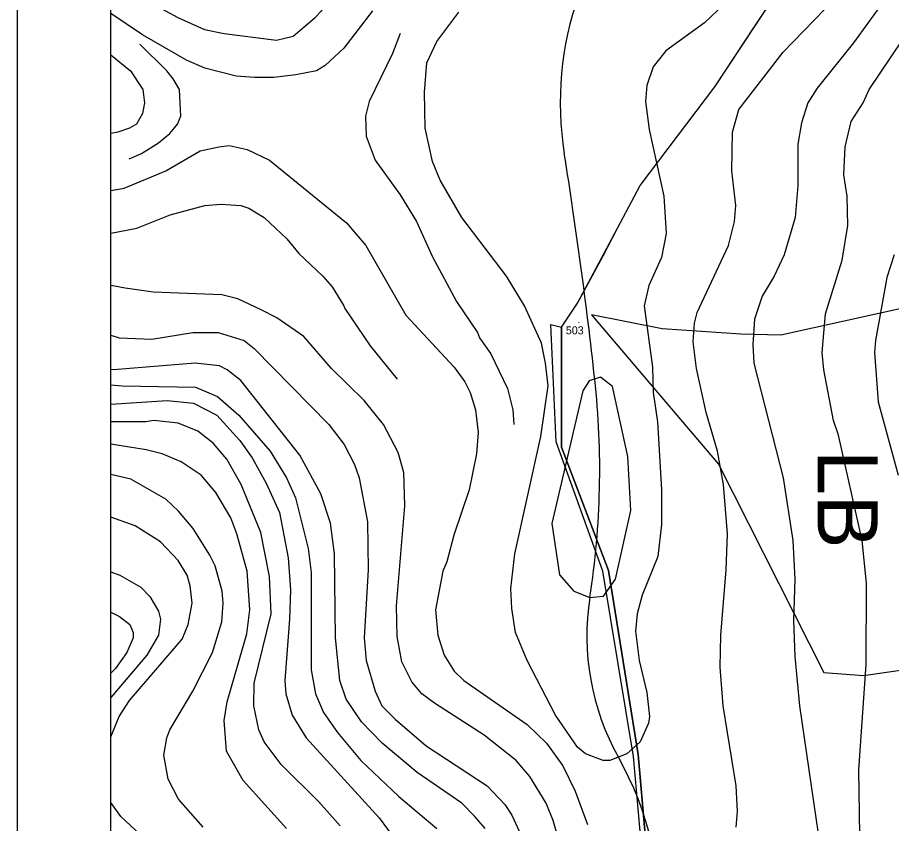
# Model space of a CAD drawing. Extents: x -510989 to -501240, y -1184665 to -1176098.
# Drawn here: x -510989 to -510334, y -1177973 to -1177369 of the extents above; entities that cross this region are included whole.
import ezdxf

# ---------------------------------------------------------------- set-up
doc = ezdxf.new("R2010")
doc.units = 0
for name, color, linetype in [('lesni_pozemek', 7, 'Continuous'), ('NAVRH_rozvodnice', 7, 'Continuous'), ('ostatni_plocha_x_ostatni_komunikace', 7, 'Continuous'), ('popis', 7, 'Continuous'), ('rozpiska', 7, 'Continuous'), ('STAV_povodi', 7, 'Continuous'), ('STAV_USES', 7, 'Continuous'), ('vrstevnice_01', 7, 'Continuous'), ('vrstevnice_02', 7, 'Continuous'), ('vrstevnice_03', 7, 'Continuous'), ('vrstevnice_05', 7, 'Continuous')]:
    doc.layers.add(name, color=color, linetype=linetype)

msp = doc.modelspace()

# ---------------------------------------------------------------- linework, layer by layer
at = {"layer": 'lesni_pozemek'}
msp.add_lwpolyline([(-510513.02, -1178041.26), (-510523.48, -1177921.32), (-510545.82, -1177783.58), (-510581, -1177691.04), (-510581, -1177601), (-510569, -1177583), (-510539, -1177527), (-510522, -1177495), (-510466, -1177421), (-510406, -1177330), (-510349, -1177235), (-510208, -1177132)], dxfattribs=at)
at = {"layer": 'NAVRH_rozvodnice'}
for centre, radius, start, end in [((-510340.47, -1177432.76), 241.56, 160.59308, 189.07504), ((-514051.77, -1178025.56), 3516.79, 6.29377, 9.07504), ((-511172.5, -1177708), 620.07, 351.11553, 6.29377), ((-510375.77, -1177832.55), 186.34, 171.11553, 209.21552), ((-510756.12, -1178045.25), 249.44, 357.5305, 29.21552)]:
    msp.add_arc(centre, radius, start, end, dxfattribs=at)
at = {"layer": 'ostatni_plocha_x_ostatni_komunikace'}
msp.add_lwpolyline([(-510522, -1177979), (-510527, -1177923), (-510550, -1177784), (-510585, -1177687), (-510589, -1177599), (-510581, -1177601), (-510581, -1177691.04), (-510545.82, -1177783.58), (-510523.48, -1177921.32), (-510513.02, -1178041.26)], dxfattribs=at)
at = {"layer": 'popis'}
msp.add_lwpolyline([(-510522, -1177979), (-510527, -1177923), (-510538.5, -1177853.5), (-510550, -1177784), (-510567.5, -1177735.5), (-510585, -1177687), (-510589, -1177599), (-510581, -1177601), (-510569, -1177583), (-510549.86, -1177547.67), (-510539, -1177527), (-510522, -1177495), (-510494, -1177458), (-510466, -1177421), (-510436, -1177375.5), (-510406, -1177330), (-510377.5, -1177282.5), (-510349, -1177235), (-510278.5, -1177183.5)], dxfattribs=at)
at = {"layer": 'rozpiska'}
for points in [[(-508019.09, -1176098), (-508019.09, -1184498), (-510989.09, -1184498), (-510989.09, -1176098)], [(-508089.09, -1176168), (-508089.09, -1184428), (-510919.09, -1184428), (-510919.09, -1176168)]]:
    msp.add_lwpolyline(points, close=True, dxfattribs=at)
at = {"layer": 'STAV_povodi'}
for centre, radius, start, end in [((-510340.47, -1177432.76), 241.56, 160.59308, 189.07504), ((-514051.77, -1178025.56), 3516.79, 6.29377, 9.07504), ((-511172.5, -1177708), 620.07, 351.11553, 6.29377), ((-510375.77, -1177832.55), 186.34, 171.11553, 209.21552), ((-510756.12, -1178045.25), 249.44, 357.5305, 29.21552)]:
    msp.add_arc(centre, radius, start, end, dxfattribs=at)
at = {"layer": 'STAV_USES'}
for p, q in [((-510321.58, -1177586.16), (-510416.72, -1177607.14)), ((-510321.58, -1177586.16), (-510416.72, -1177607.14)), ((-510505.49, -1177602.27), (-510558.69, -1177591.86)), ((-510558.69, -1177591.86), (-510463.39, -1177703.77)), ((-510505.49, -1177602.27), (-510558.69, -1177591.86)), ((-510558.69, -1177591.86), (-510463.39, -1177703.77)), ((-510446.7, -1177606.25), (-510505.49, -1177602.27)), ((-510446.7, -1177606.25), (-510505.49, -1177602.27)), ((-510416.72, -1177607.14), (-510446.7, -1177606.25)), ((-510416.72, -1177607.14), (-510446.7, -1177606.25)), ((-510463.39, -1177703.77), (-510384.43, -1177860.07)), ((-510463.39, -1177703.77), (-510384.43, -1177860.07)), ((-510354.5, -1177862.11), (-510212.14, -1177841.84)), ((-510354.5, -1177862.11), (-510212.14, -1177841.84)), ((-510384.43, -1177860.07), (-510354.5, -1177862.11)), ((-510384.43, -1177860.07), (-510354.5, -1177862.11))]:
    msp.add_line(p, q, dxfattribs=at)
at = {"layer": 'vrstevnice_01'}
for points in [[(-510919.09, -1177334.93), (-510909.69, -1177343), (-510887.41, -1177359), (-510868.81, -1177369), (-510848.91, -1177378), (-510834.19, -1177381), (-510794.91, -1177386), (-510782.31, -1177383), (-510765.91, -1177369), (-510761.19, -1177364), (-510740.69, -1177334), (-510708.69, -1177272), (-510698.41, -1177255), (-510678.59, -1177226), (-510634.41, -1177183), (-510607, -1177164), (-510577.41, -1177148), (-510557.81, -1177135), (-510513.19, -1177080), (-510493.5, -1177059)], [(-510308.31, -1177295), (-510339.69, -1177357), (-510362.09, -1177388), (-510389.31, -1177422), (-510396.31, -1177433), (-510401.19, -1177448), (-510403.81, -1177464), (-510403.81, -1177495), (-510405.81, -1177519), (-510414.09, -1177547), (-510421.59, -1177563), (-510430.59, -1177578), (-510436.31, -1177595), (-510437.59, -1177614), (-510436.81, -1177628), (-510414.81, -1177714), (-510407.5, -1177761), (-510406, -1177790), (-510407, -1177821), (-510406.09, -1177848), (-510402.5, -1177885), (-510388.69, -1177981)], [(-510459.19, -1177359), (-510473.81, -1177373), (-510502.91, -1177394), (-510512.31, -1177406), (-510517.19, -1177420), (-510518.09, -1177432), (-510515.31, -1177453), (-510504.31, -1177503), (-510502.59, -1177531), (-510506.09, -1177549), (-510515.5, -1177570), (-510519, -1177585), (-510512.91, -1177631), (-510512.31, -1177650), (-510509.19, -1177672), (-510506, -1177723), (-510506.09, -1177749), (-510508.91, -1177773), (-510520.5, -1177802), (-510524.41, -1177816), (-510525.5, -1177829), (-510522.91, -1177851), (-510517, -1177875), (-510515.19, -1177893), (-510515.81, -1177898), (-510522.19, -1177912), (-510532, -1177921), (-510544.81, -1177926), (-510549.91, -1177926), (-510563.09, -1177921)], [(-510563.09, -1177921), (-510569, -1177916), (-510585.59, -1177892), (-510606.81, -1177851), (-510615.5, -1177830), (-510618.41, -1177812), (-510619, -1177797), (-510616.19, -1177771), (-510596.5, -1177683), (-510591, -1177645), (-510593, -1177628), (-510596.19, -1177613), (-510608.91, -1177585), (-510622.31, -1177563), (-510655.81, -1177519), (-510672.09, -1177491), (-510677.81, -1177477), (-510683.31, -1177452), (-510683.81, -1177425), (-510682, -1177403), (-510674.59, -1177387), (-510658.09, -1177365)], [(-510919.09, -1177396.97), (-510904.31, -1177409), (-510895, -1177423), (-510893.81, -1177433), (-510895.31, -1177441), (-510899.91, -1177449), (-510905, -1177452), (-510913.81, -1177455), (-510919.09, -1177455.91)], [(-510331.59, -1177547), (-510337.09, -1177564), (-510345.69, -1177611), (-510346.41, -1177620), (-510343.69, -1177657), (-510328.59, -1177712)], [(-510581.91, -1177990), (-510587.31, -1177971), (-510592.5, -1177958), (-510604.91, -1177938), (-510615.19, -1177926), (-510639.09, -1177907), (-510676.41, -1177883), (-510685.81, -1177876), (-510693.31, -1177867), (-510700.91, -1177852), (-510704.41, -1177833), (-510704.81, -1177810), (-510698.59, -1177735), (-510699.41, -1177710), (-510703.69, -1177695), (-510714.69, -1177674), (-510729.19, -1177656), (-510753.69, -1177632), (-510774.41, -1177608), (-510794.59, -1177594), (-510806.31, -1177588), (-510823.91, -1177580), (-510835.91, -1177577), (-510887.31, -1177575), (-510908.41, -1177572), (-510919.09, -1177569.86)], [(-510638.41, -1177977), (-510646, -1177968), (-510655.91, -1177958), (-510689.41, -1177935), (-510715.69, -1177913), (-510731, -1177897), (-510742.59, -1177880), (-510747.31, -1177866), (-510750.5, -1177834), (-510751.31, -1177771), (-510754.41, -1177748), (-510761.5, -1177726), (-510777.41, -1177697), (-510821.69, -1177641), (-510831.81, -1177633), (-510837.59, -1177630), (-510855.81, -1177628), (-510917.19, -1177633), (-510919.09, -1177632.92)], [(-510919.09, -1177658.94), (-510876.91, -1177656), (-510857.19, -1177658), (-510839.5, -1177667), (-510822.31, -1177686), (-510813.19, -1177699), (-510802.59, -1177718), (-510792.69, -1177740), (-510786.09, -1177774), (-510784.31, -1177798), (-510785, -1177820), (-510788.69, -1177866), (-510787.81, -1177876), (-510783.09, -1177892), (-510772.5, -1177909), (-510717.81, -1177969), (-510705.41, -1177986)], [(-510787.31, -1177977), (-510819.91, -1177941), (-510832.31, -1177919), (-510834.19, -1177896), (-510831.91, -1177882), (-510817, -1177831), (-510814.91, -1177813), (-510816.81, -1177784), (-510824.5, -1177756), (-510829.19, -1177744), (-510840.31, -1177725), (-510851.41, -1177712), (-510866.41, -1177702), (-510880.69, -1177696), (-510892.59, -1177693), (-510919.09, -1177688.93)], [(-510919.09, -1177908.15), (-510912.81, -1177893), (-510905, -1177881), (-510865.5, -1177835), (-510861, -1177824), (-510858.09, -1177808), (-510859.69, -1177795), (-510861.91, -1177787), (-510868.5, -1177776), (-510881.81, -1177762), (-510900.81, -1177750), (-510919.09, -1177743.6)], [(-510919.09, -1177814.67), (-510912.59, -1177818), (-510904.81, -1177824), (-510902.41, -1177830), (-510902.41, -1177834), (-510907, -1177845), (-510915.5, -1177857), (-510919.09, -1177860.38)], [(-510878, -1177999), (-510911.5, -1177968), (-510919.09, -1177957.4)]]:
    msp.add_lwpolyline(points, dxfattribs=at)
at = {"layer": 'vrstevnice_02'}
for points in [[(-510722.81, -1177364), (-510744.41, -1177392), (-510758.41, -1177405), (-510764.81, -1177409), (-510780.31, -1177412), (-510796.81, -1177414), (-510811, -1177414), (-510825.09, -1177413), (-510848.5, -1177407), (-510862.31, -1177401), (-510895.31, -1177382), (-510919.09, -1177365.89)], [(-510450, -1177976), (-510449.09, -1177964), (-510450.09, -1177945), (-510459.91, -1177885), (-510462.19, -1177856), (-510461.69, -1177832), (-510457.5, -1177783), (-510456.5, -1177756), (-510459.69, -1177719), (-510464, -1177694), (-510472.69, -1177665), (-510479.91, -1177632), (-510482.41, -1177612), (-510481.31, -1177598), (-510479.41, -1177590), (-510455.81, -1177540), (-510451.31, -1177522), (-510450.31, -1177510), (-510453.41, -1177484), (-510452.91, -1177455), (-510448.19, -1177438), (-510414.81, -1177395), (-510383.91, -1177363)], [(-510357, -1177998), (-510358.09, -1177933), (-510352.5, -1177854), (-510352.31, -1177793), (-510355.69, -1177761), (-510373.31, -1177682), (-510377, -1177671), (-510384.31, -1177633), (-510385.59, -1177620), (-510383.19, -1177591), (-510370.59, -1177551), (-510366.31, -1177525), (-510366.81, -1177503), (-510369.41, -1177487), (-510368.41, -1177466), (-510363.91, -1177447), (-510354.81, -1177433), (-510350.41, -1177423), (-510317.41, -1177374)], [(-510919.09, -1177498.58), (-510909.19, -1177497), (-510877.91, -1177484), (-510852.09, -1177469), (-510838, -1177466), (-510830.31, -1177465), (-510816.91, -1177468), (-510800.19, -1177476), (-510742.41, -1177523), (-510727.91, -1177540), (-510697.91, -1177592), (-510661.59, -1177631), (-510653.59, -1177642), (-510649.69, -1177650), (-510645.69, -1177663), (-510643.5, -1177680), (-510644.81, -1177696), (-510650.31, -1177723), (-510661.81, -1177757), (-510667.09, -1177777), (-510670.09, -1177784), (-510675.59, -1177813), (-510673.91, -1177832), (-510669, -1177847), (-510661.5, -1177859), (-510654.31, -1177866), (-510606.91, -1177899), (-510592.31, -1177913), (-510580.09, -1177930), (-510570.81, -1177949), (-510561.59, -1177974)], [(-510919.09, -1177607.19), (-510912.91, -1177609), (-510888.31, -1177610), (-510857.5, -1177605), (-510838.69, -1177605), (-510819.09, -1177611), (-510811.5, -1177617), (-510755.59, -1177674), (-510744, -1177689), (-510736.41, -1177704), (-510732.81, -1177714), (-510726.5, -1177747), (-510726, -1177783), (-510729, -1177834), (-510727.5, -1177851), (-510720.81, -1177874), (-510715.91, -1177885), (-510705.81, -1177895), (-510682.59, -1177915), (-510636.91, -1177945), (-510623.5, -1177959), (-510618.41, -1177967), (-510608.69, -1177988)], [(-510919.09, -1177644.36), (-510910.59, -1177645), (-510855.59, -1177646), (-510839.19, -1177653), (-510823, -1177667), (-510799.59, -1177694), (-510787.41, -1177714), (-510780.59, -1177729), (-510771.09, -1177767), (-510768.91, -1177785), (-510768.91, -1177858), (-510765.5, -1177876), (-510759.5, -1177890), (-510749, -1177905), (-510731.5, -1177926), (-510703.09, -1177953), (-510674.5, -1177977)], [(-510747, -1177975), (-510763, -1177957), (-510791.31, -1177929), (-510804.09, -1177912), (-510808.19, -1177903), (-510811.91, -1177885), (-510811.5, -1177868), (-510798.81, -1177816), (-510800.19, -1177788), (-510806.69, -1177755), (-510821.41, -1177719), (-510832, -1177700), (-510842.31, -1177688), (-510853.81, -1177679), (-510868.59, -1177673), (-510886.81, -1177671), (-510892.91, -1177672), (-510918.59, -1177672), (-510919.09, -1177671.95)], [(-510849.91, -1177976), (-510868.41, -1177955), (-510876, -1177940), (-510879.31, -1177922), (-510877.09, -1177909), (-510874.81, -1177903), (-510857.59, -1177874), (-510842.91, -1177845), (-510835.91, -1177822), (-510834.81, -1177808), (-510835.69, -1177799), (-510840.81, -1177780), (-510844.81, -1177772), (-510857.41, -1177752), (-510868.31, -1177739), (-510877.91, -1177730), (-510904, -1177715), (-510919.09, -1177711.44)], [(-510919.09, -1177784.55), (-510912.41, -1177787), (-510896.59, -1177796), (-510889.81, -1177803), (-510883.31, -1177814), (-510881.81, -1177820), (-510883.31, -1177832), (-510892.09, -1177847), (-510919.09, -1177878.76)]]:
    msp.add_lwpolyline(points, dxfattribs=at)
at = {"layer": 'vrstevnice_03'}
for points in [[(-510702, -1177381), (-510707.81, -1177396), (-510725.41, -1177432), (-510728.19, -1177443), (-510727.69, -1177458), (-510720.91, -1177476), (-510702, -1177502), (-510689.81, -1177522), (-510678, -1177548), (-510659.81, -1177582), (-510644.09, -1177605), (-510642.59, -1177609), (-510634.09, -1177621), (-510621.59, -1177647), (-510617.69, -1177663), (-510616.81, -1177674)], [(-510905.31, -1177475), (-510896.19, -1177471), (-510883.41, -1177463), (-510874.81, -1177456), (-510869.19, -1177449), (-510866.69, -1177443), (-510867.59, -1177423), (-510872.31, -1177415), (-510877.09, -1177409), (-510897.41, -1177389)], [(-510919.09, -1177530.64), (-510899.59, -1177527), (-510874.5, -1177517), (-510848.69, -1177510), (-510836.41, -1177509), (-510821.59, -1177510), (-510815.59, -1177512), (-510804.19, -1177519), (-510787.19, -1177535), (-510778, -1177546), (-510760, -1177563), (-510753.09, -1177571), (-510744.31, -1177585), (-510743.69, -1177587), (-510724.59, -1177615), (-510704.31, -1177640)]]:
    msp.add_lwpolyline(points, dxfattribs=at)
msp.add_lwpolyline([(-510565, -1177648.84), (-510588.35, -1177748.21), (-510582.66, -1177786.67), (-510571.84, -1177798.96), (-510559.88, -1177803.77), (-510549.62, -1177802.7), (-510540.51, -1177789.88), (-510529.12, -1177738.59), (-510531.4, -1177697.99), (-510542.79, -1177645.64), (-510551.9, -1177638.69), (-510560.44, -1177641.36)], close=True, dxfattribs=at)

# ---------------------------------------------------------------- texts
at = {"layer": 'STAV_USES'}
msp.add_text('LB', height=45, rotation=270, dxfattribs=at).set_placement((-510388.96, -1177693.33))
at = {"layer": 'vrstevnice_05'}
for s, p in [('503', (-510577.84, -1177606.47)), ('.', (-510569.26, -1177598.06))]:
    msp.add_text(s, height=6, dxfattribs=at).set_placement(p)

doc.saveas('drawing.dxf')
